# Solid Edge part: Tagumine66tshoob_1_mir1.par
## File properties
Author: KULL
Template: Iso Metric Part.par
Last saved by: KULL
Revision: 2
Application: Solid Edge
Density: 2712,000 kg/m^3
Accuracy: 0,990
Username: KULL
Material: Aluminum, 1060
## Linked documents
Tagumine66tshoob_1.par
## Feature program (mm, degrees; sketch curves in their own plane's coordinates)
part copy "CopiedPart_1"
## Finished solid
Body 1: solid body, 578 faces, 1234 edges, 670 vertices.
  Faces by surface: blend 365, spline 59, sphere 55, plane 30, cylinder 28, torus 27, offset 13, cone 1
  Edges by curve: intersection 729, circle 467, line 37, curve on surface 1
Bounding box of the edges (mm; curved faces can reach further): 84.000 x 73.183 x 18.177, from (-384.46, -113.1829, -2.3663) to (-300.46, -40, 15.811).
Cylindrical faces by radius (mm): R0.4 x6, R1.5 x1, R2.5 x2, R2.9732 x1, R5 x4, R7 x2, R7.9504 x1, R8.5905 x1, R9.9504 x1, R10.5905 x1, R10.611 x1, R12.611 x1, R20 x2, R21.7545 x1, R22 x2, R23.7545 x1
Conical faces (half-angle, radius in mm at the cone's reference point): 40.1033 deg R3.865 x1
Toroidal faces (ring radius, tube radius in mm): R2.5732 r0.4 x2, R3.9041 r0.4 x1, R4.4 r0.6 x8, R4.5371 r1.485 x1, R4.996 r0.6 x1, R5.3 r0.3 x8, R5.7982 r0.6 x1, R6 r1 x4, R6.9857 r1 x1
Spherical faces by radius (mm): R0.1 x53, R4 x1, R6 x1
Planar faces by outward normal: +x 9, -x 9, oblique 12
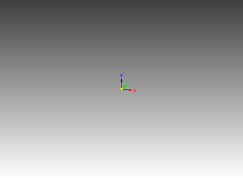
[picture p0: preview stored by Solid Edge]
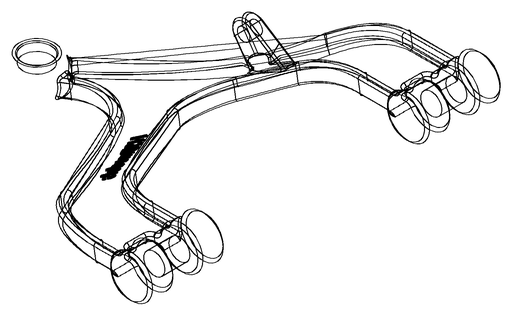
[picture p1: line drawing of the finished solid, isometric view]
